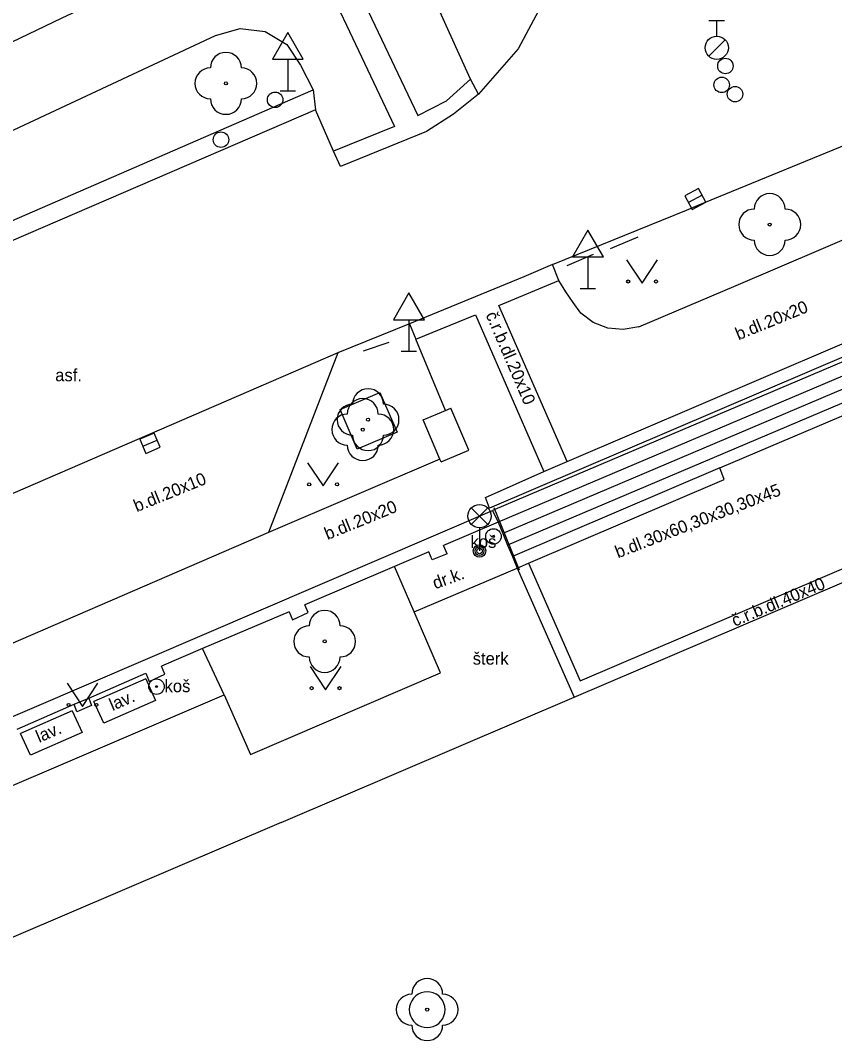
# Model space of a CAD drawing. Extents: x -600309 to -598967, y -1161267 to -1160292.
# Drawn here: x -599366.56 to -599340.27, y -1161179.27 to -1161146.33 of the extents above; entities that cross this region are included whole.
import ezdxf

# ---------------------------------------------------------------- set-up
doc = ezdxf.new("R2010")
doc.units = 0
for name, color, linetype in [('Level 10', 7, 'Continuous'), ('Level 11', 7, 'Continuous'), ('Level 22', 7, 'Continuous'), ('Level 25', 7, 'Continuous'), ('Level 26', 7, 'Continuous'), ('Level 27', 7, 'Continuous'), ('Level 28', 7, 'Continuous'), ('Level 31', 7, 'Continuous'), ('Level 33', 7, 'Continuous'), ('Level 34', 7, 'Continuous'), ('Level 36', 7, 'Continuous'), ('Level 40', 7, 'Continuous'), ('Level 42', 7, 'Continuous'), ('Level 53', 7, 'Continuous'), ('Level 7', 7, 'Continuous'), ('Level 9', 7, 'Continuous')]:
    doc.layers.add(name, color=color, linetype=linetype)

msp = doc.modelspace()

# ---------------------------------------------------------------- linework, layer by layer
at = {"layer": 'Level 10'}
for points in [[(-599349.1, -1161141.7199), (-599349.12, -1161143.6599), (-599349.59, -1161145.54), (-599350.49, -1161147.25), (-599351.77, -1161148.71)], [(-599344.68, -1161152.29), (-599333.33, -1161147.64)], [(-599351.77, -1161148.71), (-599352.58, -1161149.36), (-599353.45, -1161149.9099)], [(-599357.04, -1161149.21), (-599376.23, -1161157.49)], [(-599356.45, -1161150.55), (-599357.04, -1161149.21)], [(-599353.45, -1161149.9099), (-599356.23, -1161151.05)], [(-599356.23, -1161151.05), (-599356.45, -1161150.55)], [(-599349.38, -1161154.21), (-599345.06, -1161152.45), (-599344.68, -1161152.29)], [(-599349.38, -1161154.21), (-599350.31, -1161154.61)], [(-599350.31, -1161154.61), (-599353.09, -1161155.75)], [(-599353.09, -1161155.75), (-599354, -1161156.13)], [(-599354, -1161156.13), (-599356.31, -1161157.06)], [(-599356.31, -1161157.06), (-599358.55, -1161162.86)], [(-599358.55, -1161162.86), (-599369.86, -1161167.75)]]:
    msp.add_lwpolyline(points, dxfattribs=at)
at = {"layer": 'Level 11'}
for points in [[(-599357.05, -1161142.42), (-599353.73, -1161149.4)], [(-599357.79, -1161142.77), (-599365.23, -1161146.25), (-599382.09, -1161154.35)], [(-599357.79, -1161142.77), (-599354.49, -1161149.75)], [(-599352.03, -1161148.23), (-599353.02, -1161146.04)], [(-599360.26, -1161146.81), (-599359.4699, -1161146.59), (-599358.6599, -1161146.69), (-599357.96, -1161147.11), (-599357.52, -1161147.77)], [(-599376.4099, -1161156.95), (-599377.46, -1161154.86), (-599360.26, -1161146.81)], [(-599357.52, -1161147.77), (-599357.11, -1161148.57)], [(-599353.73, -1161149.4), (-599352.81, -1161148.92), (-599352.03, -1161148.23)], [(-599351.77, -1161148.71), (-599352.03, -1161148.23)], [(-599376.4099, -1161156.95), (-599357.11, -1161148.57)], [(-599357.11, -1161148.57), (-599357.04, -1161149.21)], [(-599343.45, -1161154.89), (-599329.73, -1161149.02)], [(-599354.49, -1161149.75), (-599356.45, -1161150.55)], [(-599348.91, -1161160.57), (-599329.44, -1161152.24)], [(-599329.36, -1161152.65), (-599351.42, -1161162.08)], [(-599349.18, -1161154.73), (-599349.38, -1161154.21)], [(-599351.12, -1161155.53), (-599349.18, -1161154.73)], [(-599348.47, -1161155.78), (-599348.72, -1161155.44), (-599348.95, -1161155.09), (-599349.18, -1161154.73)], [(-599346.6, -1161156.22), (-599343.45, -1161154.89)], [(-599348.91, -1161160.57), (-599351.12, -1161155.53)], [(-599353.8, -1161156.62), (-599351.87, -1161155.84)], [(-599351.87, -1161155.84), (-599349.66, -1161160.89)], [(-599346.6, -1161156.22), (-599347.1, -1161156.31), (-599347.6, -1161156.27), (-599348.07, -1161156.08), (-599348.47, -1161155.78)], [(-599354, -1161156.13), (-599353.8, -1161156.62)], [(-599352.84, -1161158.92), (-599353.8, -1161156.62)], [(-599338.77, -1161156.82), (-599351.32, -1161162.15)], [(-599356.31, -1161157.06), (-599390.54, -1161171.87)], [(-599338.6, -1161157.21), (-599351.14, -1161162.53)], [(-599338.44, -1161157.57), (-599350.99, -1161162.9)], [(-599338.28, -1161157.94), (-599350.84, -1161163.27)], [(-599354.96, -1161158.34), (-599354.4, -1161159.62), (-599355.69, -1161160.17), (-599356.24, -1161158.89), (-599354.96, -1161158.34)], [(-599343.98, -1161160.78), (-599338.13, -1161158.29)], [(-599353.56, -1161159.23), (-599352.84, -1161158.92)], [(-599353.02, -1161160.49), (-599353.56, -1161159.23)], [(-599353.02, -1161160.49), (-599358.55, -1161162.86)], [(-599343.98, -1161160.78), (-599350.68, -1161163.64)], [(-599349.66, -1161160.89), (-599348.91, -1161160.57)], [(-599343.84, -1161161.15), (-599343.98, -1161160.78)], [(-599351.55, -1161161.73), (-599349.66, -1161160.89)], [(-599350.16, -1161163.85), (-599343.84, -1161161.15)], [(-599348.49, -1161167.65), (-599333.93, -1161161.43)], [(-599351.42, -1161162.08), (-599351.55, -1161161.73)], [(-599348.68, -1161168.18), (-599333.77, -1161161.81)], [(-599351.14, -1161162.53), (-599350.99, -1161162.9)], [(-599350.99, -1161162.9), (-599350.84, -1161163.27)], [(-599350.84, -1161163.27), (-599350.68, -1161163.64)], [(-599350.68, -1161163.64), (-599350.52, -1161164.02)], [(-599353, -1161167.4), (-599353.85, -1161165.42), (-599354.48, -1161163.96)], [(-599353.85, -1161165.42), (-599350.52, -1161164.02)], [(-599350.52, -1161164.02), (-599350.16, -1161163.85)], [(-599350.52, -1161164.02), (-599348.68, -1161168.18)], [(-599350.16, -1161163.85), (-599348.49, -1161167.65)], [(-599359.99, -1161168.1), (-599360.68, -1161166.61)], [(-599359.14, -1161170.03), (-599353, -1161167.4)], [(-599372.11, -1161173.29), (-599359.99, -1161168.1)], [(-599359.99, -1161168.1), (-599359.14, -1161170.03)], [(-599364.74, -1161168.65), (-599364.83, -1161168.41)], [(-599364.36, -1161168.21), (-599364.27, -1161168.45)], [(-599358.15, -1161172.23), (-599348.68, -1161168.18)], [(-599364.27, -1161168.45), (-599364.74, -1161168.65)], [(-599358.15, -1161172.23), (-599370.21, -1161177.38)], [(-599352.8522, -1161178.27), (-599352.861, -1161178.1697), (-599352.887, -1161178.0724), (-599352.9296, -1161177.9811), (-599352.9874, -1161177.8986), (-599353.0586, -1161177.8274), (-599353.1411, -1161177.7696), (-599353.2324, -1161177.727), (-599353.3297, -1161177.701), (-599353.43, -1161177.6922), (-599353.5303, -1161177.701), (-599353.6276, -1161177.727), (-599353.7189, -1161177.7696), (-599353.8014, -1161177.8274), (-599353.8726, -1161177.8986), (-599353.9304, -1161177.9811), (-599353.973, -1161178.0724), (-599353.999, -1161178.1697), (-599354.0078, -1161178.27), (-599353.999, -1161178.3703), (-599353.973, -1161178.4676), (-599353.9304, -1161178.5589), (-599353.8726, -1161178.6414), (-599353.8014, -1161178.7126), (-599353.7189, -1161178.7704), (-599353.6276, -1161178.813), (-599353.5303, -1161178.839), (-599353.43, -1161178.8478), (-599353.3297, -1161178.839), (-599353.2324, -1161178.813), (-599353.1411, -1161178.7704), (-599353.0586, -1161178.7126), (-599352.9874, -1161178.6414), (-599352.9296, -1161178.5589), (-599352.887, -1161178.4676), (-599352.861, -1161178.3703), (-599352.8522, -1161178.27)]]:
    msp.add_lwpolyline(points, dxfattribs=at)
at = {"layer": 'Level 22'}
for centre in [(-599359.93, -1161148.36), (-599342.37, -1161152.92), (-599355.34, -1161159.2199), (-599355.51, -1161159.54), (-599356.74, -1161166.38), (-599353.43, -1161178.27)]:
    msp.add_circle(centre, 0.05, dxfattribs=at)
for centre, start, end in [((-599359.93, -1161147.86), 0, 180), ((-599360.43, -1161148.36), 90, 270), ((-599359.43, -1161148.36), 270, 90), ((-599359.93, -1161148.86), 180, 0), ((-599342.37, -1161152.42), 0, 180), ((-599342.87, -1161152.92), 90, 270), ((-599341.87, -1161152.92), 270, 90), ((-599342.37, -1161153.42), 180, 0), ((-599355.34, -1161158.7199), 0, 180), ((-599355.51, -1161159.04), 0, 180), ((-599355.84, -1161159.2199), 90, 270), ((-599354.84, -1161159.2199), 270, 90), ((-599356.01, -1161159.54), 90, 270), ((-599355.01, -1161159.54), 270, 90), ((-599355.34, -1161159.7199), 180, 0), ((-599355.51, -1161160.04), 180, 0), ((-599356.74, -1161165.88), 0, 180), ((-599357.24, -1161166.38), 90, 270), ((-599356.24, -1161166.38), 270, 90), ((-599356.74, -1161166.88), 180, 0), ((-599353.43, -1161177.77), 0, 180), ((-599353.93, -1161178.27), 90, 270), ((-599352.93, -1161178.27), 270, 90), ((-599353.43, -1161178.77), 180, 0)]:
    msp.add_arc(centre, 0.5, start, end, dxfattribs=at)
at = {"layer": 'Level 25'}
for centre, radius in [((-599351.29, -1161162.99), 0.25), ((-599351.29, -1161162.99), 0.0303), ((-599362.17, -1161167.84), 0.25), ((-599362.17, -1161167.84), 0.0303)]:
    msp.add_circle(centre, radius, dxfattribs=at)
at = {"layer": 'Level 26'}
for points in [[(-599352.84, -1161158.92), (-599352.67, -1161158.85)], [(-599352.09, -1161160.2), (-599352.67, -1161158.85)], [(-599352.98, -1161160.58), (-599352.09, -1161160.2)], [(-599352.98, -1161160.58), (-599353.02, -1161160.49)]]:
    msp.add_lwpolyline(points, dxfattribs=at)
at = {"layer": 'Level 27'}
for p, q in [((-599344.5497, -1161151.9718), (-599344.9903, -1161152.2082)), ((-599362.61, -1161160.078), (-599362.15, -1161159.882))]:
    msp.add_line(p, q, dxfattribs=at)
for points in [[(-599344.6678, -1161151.7515), (-599345.1085, -1161151.9878), (-599344.8722, -1161152.4285), (-599344.4315, -1161152.1922)], [(-599362.512, -1161160.308), (-599362.052, -1161160.112), (-599362.248, -1161159.652), (-599362.708, -1161159.848)]]:
    msp.add_lwpolyline(points, close=True, dxfattribs=at)
at = {"layer": 'Level 28'}
for p, q in [((-599344.33, -1161146.335), (-599343.83, -1161146.335)), ((-599344.08, -1161146.835), (-599344.08, -1161146.335)), ((-599344.338, -1161147.482), (-599343.808, -1161146.952))]:
    msp.add_line(p, q, dxfattribs=at)
for centre, radius in [((-599344.08, -1161147.21), 0.375), ((-599343.8, -1161147.8), 0.25), ((-599343.92, -1161148.41), 0.25), ((-599343.49, -1161148.71), 0.25)]:
    msp.add_circle(centre, radius, dxfattribs=at)
at = {"layer": 'Level 31'}
for centre in [(-599358.34, -1161148.89), (-599360.09, -1161150.18)]:
    msp.add_circle(centre, 0.25, dxfattribs=at)
at = {"layer": 'Level 33'}
for p, q in [((-599352.005, -1161162.6), (-599351.475, -1161162.07)), ((-599352.005, -1161162.07), (-599351.475, -1161162.6)), ((-599351.74, -1161162.71), (-599351.74, -1161163.46))]:
    msp.add_line(p, q, dxfattribs=at)
for centre, radius in [((-599351.74, -1161162.335), 0.375), ((-599351.74, -1161163.46), 0.2), ((-599351.74, -1161163.46), 0.1445), ((-599351.74, -1161163.46), 0.0876)]:
    msp.add_circle(centre, radius, dxfattribs=at)
at = {"layer": 'Level 34'}
for p, q in [((-599357.93, -1161147.582), (-599357.93, -1161148.6)), ((-599358.18, -1161148.6), (-599357.68, -1161148.6)), ((-599348.24, -1161153.962), (-599348.24, -1161154.98)), ((-599348.49, -1161154.98), (-599347.99, -1161154.98)), ((-599354.02, -1161155.992), (-599354.02, -1161157.01)), ((-599354.27, -1161157.01), (-599353.77, -1161157.01))]:
    msp.add_line(p, q, dxfattribs=at)
for points in [[(-599358.43, -1161147.582), (-599357.43, -1161147.582), (-599357.93, -1161146.716)], [(-599348.74, -1161153.962), (-599347.74, -1161153.962), (-599348.24, -1161153.096)], [(-599354.52, -1161155.992), (-599353.52, -1161155.992), (-599354.02, -1161155.126)]]:
    msp.add_lwpolyline(points, close=True, dxfattribs=at)
at = {"layer": 'Level 36'}
for points in [[(-599346.99, -1161154.06), (-599346.49, -1161154.81), (-599345.99, -1161154.06)], [(-599357.29, -1161160.61), (-599356.79, -1161161.36), (-599356.29, -1161160.61)], [(-599357.21, -1161167.19), (-599356.71, -1161167.94), (-599356.21, -1161167.19)], [(-599365.06, -1161167.73), (-599364.56, -1161168.48), (-599364.06, -1161167.73)]]:
    msp.add_lwpolyline(points, dxfattribs=at)
for centre in [(-599346.9402, -1161154.7598), (-599346.0408, -1161154.7598), (-599357.2402, -1161161.3098), (-599356.3408, -1161161.3098), (-599357.1602, -1161167.8898), (-599356.2608, -1161167.8898), (-599365.0102, -1161168.4298), (-599364.1108, -1161168.4298)]:
    msp.add_circle(centre, 0.05, dxfattribs=at)
at = {"layer": 'Level 53'}
for points in [[(-599362.52, -1161167.59), (-599364.19, -1161168.32)], [(-599362.52, -1161167.59), (-599362.2, -1161168.29)], [(-599363.87, -1161169.02), (-599364.19, -1161168.32)], [(-599362.2, -1161168.29), (-599363.87, -1161169.02)], [(-599364.89, -1161168.62), (-599366.56, -1161169.35)], [(-599364.89, -1161168.62), (-599364.57, -1161169.32)], [(-599366.24, -1161170.05), (-599366.56, -1161169.35)], [(-599364.57, -1161169.32), (-599366.24, -1161170.05)]]:
    msp.add_lwpolyline(points, dxfattribs=at)
at = {"layer": 'Level 7'}
for points in [[(-599371.84, -1161170.96), (-599351.32, -1161162.15)], [(-599351.32, -1161162.15), (-599351.14, -1161162.53)], [(-599351.14, -1161162.53), (-599352.9, -1161163.28)], [(-599353.38, -1161163.49), (-599354.48, -1161163.96), (-599357.38, -1161165.2)], [(-599353.27, -1161163.75), (-599353.38, -1161163.49)], [(-599352.78, -1161163.55), (-599352.9, -1161163.28)], [(-599352.78, -1161163.55), (-599353.27, -1161163.75)], [(-599357.89, -1161165.42), (-599360.68, -1161166.61)], [(-599357.89, -1161165.42), (-599357.78, -1161165.68)], [(-599357.78, -1161165.68), (-599357.27, -1161165.45)], [(-599357.27, -1161165.45), (-599357.38, -1161165.2)], [(-599360.68, -1161166.61), (-599362.01, -1161167.18)], [(-599366.67, -1161169.21), (-599364.83, -1161168.41), (-599364.36, -1161168.21), (-599362.52, -1161167.41)], [(-599362.52, -1161167.41), (-599362.41, -1161167.67)], [(-599362.41, -1161167.67), (-599361.9, -1161167.44)], [(-599361.9, -1161167.44), (-599362.01, -1161167.18)]]:
    msp.add_lwpolyline(points, dxfattribs=at)
at = {"layer": 'Level 9'}
for points in [[(-599347.51, -1161153.69), (-599346.62, -1161153.32)], [(-599348.91, -1161154.24), (-599348.06, -1161153.88)], [(-599355.49, -1161157), (-599354.66, -1161156.72)], [(-599350.45, -1161164.08), (-599351.27, -1161162.07)]]:
    msp.add_lwpolyline(points, dxfattribs=at)

# ---------------------------------------------------------------- texts
at = {"layer": 'Level 40'}
for s, rotation, p in [('b.dl.20x20', 22.14837, (-599343.38, -1161156.66)), ('č.r.b.dl.20x10', 293.23295, (-599351.55, -1161155.83)), ('b.dl.20x10', 22.14837, (-599362.81, -1161162.21)), ('b.dl.30x60,30x30,30x45', 21.21217, (-599347.27, -1161163.7)), ('b.dl.20x20', 22.14837, (-599356.65, -1161163.11)), ('dr.k.', 20.03721, (-599353.17, -1161164.7)), ('č.r.b.dl.40x40', 22.84591, (-599343.5, -1161165.91))]:
    msp.add_text(s, height=0.39999, rotation=rotation, dxfattribs=at).set_placement(p)
for s, p in [('asf.', (-599365.44, -1161157.98)), ('šterk', (-599351.96, -1161167.13))]:
    msp.add_text(s, height=0.39999, dxfattribs=at).set_placement(p)
at = {"layer": 'Level 42'}
for p in [(-599352.03, -1161163.36), (-599361.91, -1161168.02)]:
    msp.add_text('koš', height=0.39999, dxfattribs=at).set_placement(p)
for p in [(-599363.59, -1161168.63), (-599365.96, -1161169.66)]:
    msp.add_text('lav.', height=0.39999, rotation=23.28193, dxfattribs=at).set_placement(p)

doc.saveas('drawing.dxf')
